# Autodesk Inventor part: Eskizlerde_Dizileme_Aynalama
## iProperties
Created: 2009-12
Part Number: Eskizlerde_Dizileme_Aynalama
Document SubType Name: Modeling
Designer: bulent
Density: 1 g/cm^3
Author: bulent
